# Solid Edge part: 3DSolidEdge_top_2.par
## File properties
Author: Administrator
Template: Normal.par
Last saved by: Administrator
Revision: 5
Application: Solid Edge
Accuracy: 0.990
Agile_Description: Top 2 (for diamond control pad)
Modeled_By: L. Conard
Part_Number: ITEM-SE-00009
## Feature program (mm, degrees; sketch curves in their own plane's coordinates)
body "unnamed Body 1"
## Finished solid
Body 1: solid body, 179 faces, 457 edges, 284 vertices.
  Faces by surface: plane 117, cylinder 45, torus 13, sphere 4
  Edges by curve: line 358, circle 85, spline 6, curve on surface 4, ellipse 4
Bounding box of the edges (mm; curved faces can reach further): 64.000 x 105.000 x 12.500, from (0, 0, -10.5) to (64, 105, 2).
Cylindrical faces by radius (mm): R0.25 x8, R0.75 x3, R1 x6, R2.5 x10, R2.54 x4, R2.75 x4, R4 x8, R5 x2
Toroidal faces (ring radius, tube radius in mm): R0.04 r2.5 x4, R1.25 r0.25 x4, R5 r2.5 x3, R5.25 r0.25 x2
Spherical faces by radius (mm): R4 x4
Planar faces by outward normal: +x 12, +y 15, +z 7, -x 16, -y 18, -z 7, oblique 42
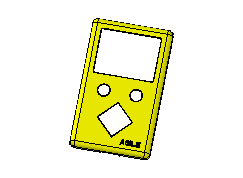
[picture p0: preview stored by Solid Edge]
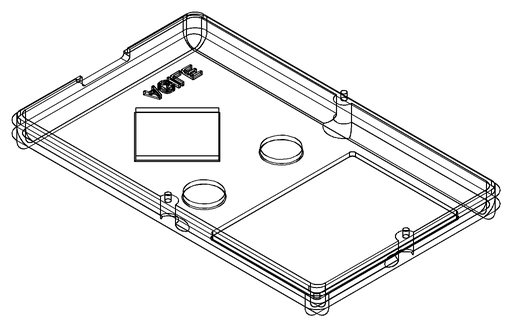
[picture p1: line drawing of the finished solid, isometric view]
